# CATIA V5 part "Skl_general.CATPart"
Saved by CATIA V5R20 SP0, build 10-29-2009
Part number: skl_general
Bounding box of the stored display mesh (mm): x 0 to 0, y -16.358 to 52.685, z -81.982 to 28.168
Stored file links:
  C:\Users\ASUS\Desktop\Think Motion IAO\Skl_general.CATPart
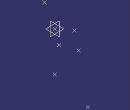
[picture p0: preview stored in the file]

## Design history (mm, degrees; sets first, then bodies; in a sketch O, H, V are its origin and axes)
Parameters
  OA = 20 mm
  OB = 40 mm {= 2*OA}
  CB = 25 mm {= 1.25*OA}
  AC = 40 mm {= 2*OA}
  DE = 130 mm {= 6.5*OA}
  GE = 56 mm {= 2.8*OA}
  OD = 52.4 mm {= 2.62*OA}
  AG = 63 mm {= 3.15*OA}
  BD = 50 mm {= 2.5*OA}
Body1 (main body)
  Plane1 "Plan_de_reference": type Offset, RefPlane yz-plane, Offset 0
  Point1 "Point.A": (0, 0, 0)
  Circle1: type CtrRad, Start 0, End 180, Center Point1, Support yz-plane, Radius 20 {= OA}, FirstDirection (0, 1, 0)
  Point2 "Point.O": type OnCurve, Support Circle1, RefPoint {extremum Reference Circle1, Direction (1, 2, 3)}, Length 81.769
  Circle2: type CtrRad, Start 0, End 180, Center Point1, Support yz-plane, Radius 40 {= AC}, FirstDirection (0, 1, 0)
  Point3 "Point.C": type OnCurve, Support Circle2, RefPoint {extremum Reference Circle2, Direction (1, 2, 3)}, Length 200.993
  Circle3: type CtrRad, Start 0, End 180, Center Point2, Support yz-plane, Radius 40 {= OB}, FirstDirection (0, 1, 0)
  Circle4: type CtrRad, Start 0, End 180, Center Point3, Support yz-plane, Radius 25 {= CB}, FirstDirection (0, 1, 0)
  Intersect1: ToIntersect1 Circle4, ToIntersect2 Circle3
  Extract1 "Point.B": ExtractElem vertex of Intersect1
  Circle5: type CtrRad, Start 0, End 180, Center Point1, Support yz-plane, Radius 63 {= AG}, FirstDirection (0, 1, 0)
  Point4 "Point.G": type OnCurve, Support Circle5, RefPoint {extremum Reference Circle5, Direction (1, 2, 3)}, Length 234.965
  Circle6: type CtrRad, Start 0, End 180, Center Point2, Support yz-plane, Radius 52.4 {= OD}, FirstDirection (0, 1, 0)
  Circle7: type CtrRad, Start 0, End 180, Center Extract1, Support yz-plane, Radius 50 {= BD}, FirstDirection (0, 1, 0)
  Intersect2: ToIntersect1 Circle7, ToIntersect2 Circle6
  Extract2 "Point.D": ExtractElem vertex of Intersect2
  Circle8: type CtrRad, Start 0, End 180, Center Extract2, Support yz-plane, Radius 130 {= DE}, FirstDirection (0, 1, 0)
  Circle9: type CtrRad, Start 0, End 180, Center Point4, Support yz-plane, Radius 56 {= GE}, FirstDirection (0, 1, 0)
  Intersect3: ToIntersect1 Circle8, ToIntersect2 Circle9
  Extract3 "Point.E": ExtractElem vertex of Intersect3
